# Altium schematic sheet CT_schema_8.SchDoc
size 277 x 170 mm
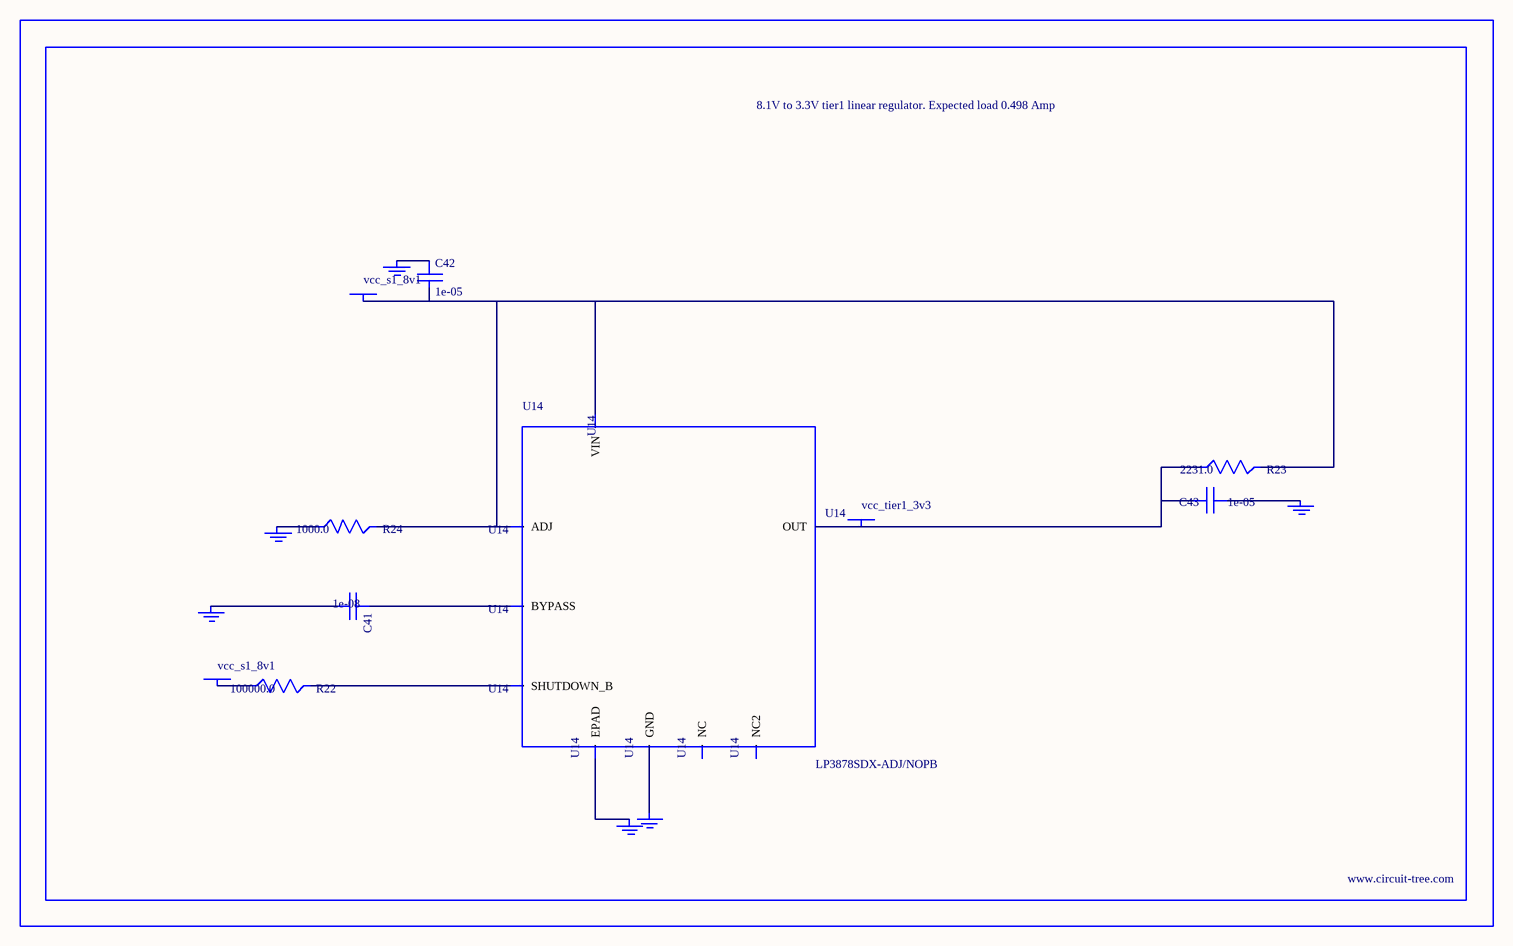
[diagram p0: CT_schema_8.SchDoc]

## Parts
BORDER7  (no value)
C41  1e-08  [C0402]
C42  1e-05  [C1206]
C43  1e-05  [C1210]
GND_INSTANCE_7_0  (no value)
GND_INSTANCE_7_1  (no value)
GND_INSTANCE_7_2  (no value)
GND_INSTANCE_7_3  (no value)
GND_INSTANCE_7_4  (no value)
GND_INSTANCE_7_5  (no value)
POWER_INSTANCE_7_0  vcc_s1_8v1
POWER_INSTANCE_7_1  vcc_s1_8v1
POWER_INSTANCE_7_2  vcc_tier1_3v3
R22  100000.0  [R0603]
R23  2231.0  [R0603]
R24  1000.0  [R0603]
U14  LP3878SDX-ADJ/NOPB  [WSON-8]

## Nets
NetC41_1: C41.1 U14.1(BYPASS)
NetC41_2: C41.2 GND_INSTANCE_7_0.0(GND)
NetC42_1: C42.1 GND_INSTANCE_7_1.0(GND)
NetC42_2: C42.2 POWER_INSTANCE_7_0.0(PWR) R23.2 R24.2 U14.4(VIN) U14.6(ADJ)
NetC43_1: C43.1 GND_INSTANCE_7_2.0(GND)
NetC43_2: C43.2 POWER_INSTANCE_7_2.0(PWR) R23.1 U14.5(OUT)
NetGND_INSTANCE_7_3_0: GND_INSTANCE_7_3.0(GND) R24.1
NetGND_INSTANCE_7_4_0: GND_INSTANCE_7_4.0(GND) U14.PAD(EPAD)
NetGND_INSTANCE_7_5_0: GND_INSTANCE_7_5.0(GND) U14.3(GND)
NetPOWER_INSTANCE_7_1_0: POWER_INSTANCE_7_1.0(PWR) R22.1
NetR22_2: R22.2 U14.8(SHUTDOWN_B)

Not connected (* = marked no-connect by the designer): U14 2(NC) 7(NC2)

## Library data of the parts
BORDER7 = BORDER_PAGE7
C41 = C0402C103K3RAC
C42 = C1206C106K3RACTU
C43 = GRM32DR61E106MA12L
GND_INSTANCE_7_0-GND_INSTANCE_7_5 = GND
POWER_INSTANCE_7_0-POWER_INSTANCE_7_2 = PWR
R22 = RC0603JR-07100KL
R23 = R23
R24 = RC0603JR-071KL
